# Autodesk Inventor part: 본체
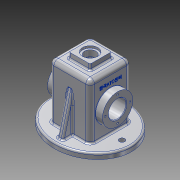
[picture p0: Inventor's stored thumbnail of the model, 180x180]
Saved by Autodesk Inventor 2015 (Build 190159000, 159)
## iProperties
Created: 2017-07
Part Number: 본체
Material: 알루미늄 6061
Document SubType Name: Modeling
Designer: C03
Density: 2.7 g/cm^3
Appearance: 알루미늄 - 평지
Mass: 889.47 g
Surface Area: 987.451 cm^2
Volume: 329.433 cm^3
Author: C03
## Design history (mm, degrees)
sketch "스케치1"
  geometry: L1 (0, 0)-(0, 65); L2 (0, 0)-(-75, 0); 2 further points; 1 other entity
  constraints: 4 end point, 2 coincident, 2 horizontal, 1 vertical, 4 other
  dimensions: "d1" = 65 distance of L1.start L1.end; "d2" = 75 distance of L1.start L2.end
extrude "돌출1" new body sketch "스케치1" distance "d3" = 10; taper "d4" = 0 deg
sketch "스케치2"
  geometry: L1 (-37, 37)-(37, 37); L2 (37, 37)-(37, -37); L3 (37, -37)-(-37, -37); L4 (-37, -37)-(-37, 37); L5 (-37, 37)-(37, -37); L6 (37, 37)-(-37, -37); 1 further point
  constraints: 12 end point, 2 midpoint, 2 parallel, 1 horizontal, 1 perpendicular
  dimensions: "d5" = 74 distance of L2.end L3.end; "d6" = 74 distance of L1.end L2.end
extrude "돌출2" join sketch "스케치2" distance "d7" = 100; taper "d8" = 0 deg
sketch "스케치4"
  geometry: L1 (32, -32)-(-32, -32); L2 (-32, -32)-(-32, 32); L3 (-32, 32)-(32, 32); L4 (32, 32)-(32, -32); L5 (32, -32)-(-32, 32); L6 (-32, -32)-(32, 32); 1 further point
  constraints: 12 end point, 2 midpoint, 2 parallel, 1 horizontal, 1 perpendicular
  dimensions: "d11" = 64 distance of L2.end L3.end; "d12" = 64 distance of L1.end L2.end
extrude "돌출3" cut sketch "스케치4" distance "d13" = 105; taper "d14" = 0 deg
node "작업 평면1"
sketch "스케치5"
  geometry: L1 (0, 0)-(0, 100) reference; L2 (-13, 45)-(-13, 72.5); L3 (-13, 72.5)-(5, 72.5); L4 (5, -10)-(5, 95) reference; L5 (5, 45)-(12, 45); L6 (12, 45)-(12, 65.5); L7 (5, 72.5)-(12, 65.5); L8 (5, 72.5)-(12, 72.5); L9 (87, 72.5)-(69, 72.5); L10 (69, 72.5)-(62, 65.5); L11 (62, 45)-(62, 65.5); L12 (87, 45)-(87, 72.5); L13 (-13, 45)-(12, 45); L14 (62, 45)-(87, 45); L15 (5, 72.5)-(5, 17.5); L16 (69, 72.5)-(69, 17.5); L17 (69, -10)-(69, 95) reference; 1 further point
  constraints: 28 end point, 5 point on line, 3 horizontal, 3 parallel, 3 perpendicular, 1 vertical
  dimensions: "d16" = 100 distance of L2.start L12.start; "d17" = 27.5 distance of L2.start L2.end; "d18" = 18 distance of L2.end L3.end; "d21" = 7 distance of L5.start L5.end; "d22" = 45 deg angle of L7 L8; "d23" = 13 distance between parallel lines of L1 L2; "d24" = 57 distance between parallel lines of L11 L4; "d26" = 35.70889 distance from line of point (37, -10) L10; "d27" = 27.5 distance from line of L11.start L9; "d28" = 82 distance between parallel lines of L12 L4; "d29" = 82.5 distance from line of point (37, -10) L9; "d112" = 55 distance of L3.end L15.end; "d113" = 55 distance of L9.end L16.end
revolve "회전1" sketch "스케치5" stored, may be unused: angle "d30" = 90 deg
sketch "스케치6"
  geometry: C1 r 27.5 at (0, 0) reference; C2 r 20.5 at (0, 0) reference; C3 r 16 at (0, 0); 1 further point
  constraints: 1 centre point, 1 coincident
  dimensions: "d31" = 32 diameter of C3
extrude "돌출4" cut sketch "스케치6" stored distance "d32" = 105; taper "d33" = 0 deg
sketch "스케치7"
  geometry: L1 (-17, 20)-(17, 20); L2 (20, 17)-(20, -17); L3 (17, -20)-(-17, -20); L4 (-20, -17)-(-20, 17); L5 (-20, 20)-(20, -20); L6 (20, 20)-(-20, -20); A1 r 3 centre (-17, 17) between (-17, 20) and (-20, 17); A2 r 3 centre (17, 17) between (20, 17) and (17, 20); A3 r 3 centre (17, -17) between (17, -20) and (20, -17); A4 r 3 centre (-17, -17) between (-20, -17) and (-17, -20); 1 further point
  constraints: 12 end point, 8 point on circle, 8 point on line, 8 tangent, 4 centre point, 3 equal radius, 2 midpoint, 2 parallel, 1 horizontal, 1 perpendicular
  dimensions: "d34" = 40 distance of L5.end L6.end; "d35" = 40 distance of L6.start L5.end; "d49" = 3 radius of A1
extrude "돌출7" join sketch "스케치7" distance "d50" = 10; taper "d51" = -5 deg
sketch "스케치11"
  geometry: 2 further points
  constraints: 1 coincident
hole "구멍2" sketch "스케치11" at (0, 0) diameter "d52" = 21; stored, may be unused: countersink angle "d56" = 90 deg, drill point angle "d58" = 0 deg; dims "d53" = 6, "d54" = 28, "d55" = 4, "d57" = 15
node "작업 평면2"
sketch "스케치12"
  geometry: L1 (-3.558, -18.887)-(80.394, 2.044) reference; L2 (-3.558, -18.887)-(-3.558, 2.044); L3 (-3.558, 2.044)-(80.394, 2.044)
  constraints: 6 end point, 1 perpendicular, 1 vertical, 1 other
  dimensions: "d65" = 86.52141 distance of L1.end L1.start
extrude "돌출8" join sketch "스케치12" stored distance "d66" = 10; taper "d67" = 0 deg
sketch "스케치13"
  geometry: L1 (0, 0)-(58, 0); L2 (0, 0)-(-58, 0); 2 further points
  constraints: 4 end point, 2 coincident, 2 horizontal
  dimensions: "d68" = 58 distance of L1.start L1.end; "d69" = 58 distance of L1.start L2.end
hole "구멍3" sketch "스케치13" at (58, 0), (-58, 0) diameter "d70" = 10; stored, may be unused: countersink angle "d74" = 90 deg, drill point angle "d76" = 0 deg; dims "d71" = 6, "d72" = 28, "d73" = 4, "d75" = 15
sketch "스케치14"
  geometry: L1 (0, 0)-(-22.5, 0); C1 r 16 at (0, 0) reference; 2 further points
  constraints: 2 end point, 1 coincident, 1 horizontal
  dimensions: "d77" = 22.5 distance of L1.start L1.end
hole "구멍4" sketch "스케치14" at (-22.5, 0) diameter "d78" = 3.242; stored, may be unused: countersink angle "d82" = 90 deg, drill point angle "d84" = 118 deg; dims "d79" = 8, "d80" = 4, "d81" = 4, "d83" = 10
sketch "스케치15"
  geometry: L1 (0, 0)-(22.5, 0); C1 r 16 at (0, 0) reference; C2 r 27.5 at (0, 0) reference; C3 r 1.621 at (22.5, 0) reference; 2 further points
  constraints: 2 end point, 1 coincident, 1 horizontal
  dimensions: "d88" = 22.5 distance of L1.start L1.end (derived)
hole "구멍5" sketch "스케치15" at (22.5, 0) diameter "d89" = 3.242; stored, may be unused: countersink angle "d93" = 90 deg, drill point angle "d95" = 118 deg; dims "d90" = 8, "d91" = 4, "d92" = 4, "d94" = 10
fillet "모깎기3" dims "d99" = 0.5, "d100" = 3
fillet "모깎기4" dims "d101" = 8
fillet "모깎기5" dims "d102" = 3
fillet "모깎기6" dims "d103" = 3
fillet "모깎기7" dims "d104" = 3
chamfer "모따기1" distance "d105" = 1; stored, may be unused: second distance "d106" = 2, angle "d107" = 45 deg
sketch "스케치16"
  geometry: L1 (-18, 46)-(-18, 12) reference; L2 (89, 66)-(0, 66) reference; 2 further points
  constraints: 1 other
  dimensions: "d108" = 30 distance from line of L1 point (12, 29); "d109" = 37 distance from line of point (12, 29) L2
feature "엠보싱1" sketch "스케치16" dims "d1" = 65, "d2" = 75, "d12" = 64, "d110" = 0.5, "d111" = 0
node "솔리드1"
mirror "대칭1"
pattern_circular "원형 패턴1" dims angle "d86" = 360 deg
pattern_circular "원형 패턴2" dims angle "d97" = 360 deg
node "투영된 루프1"
node "투영된 루프4"
other parameters: "d15" = 55, "d25" = 27.5
